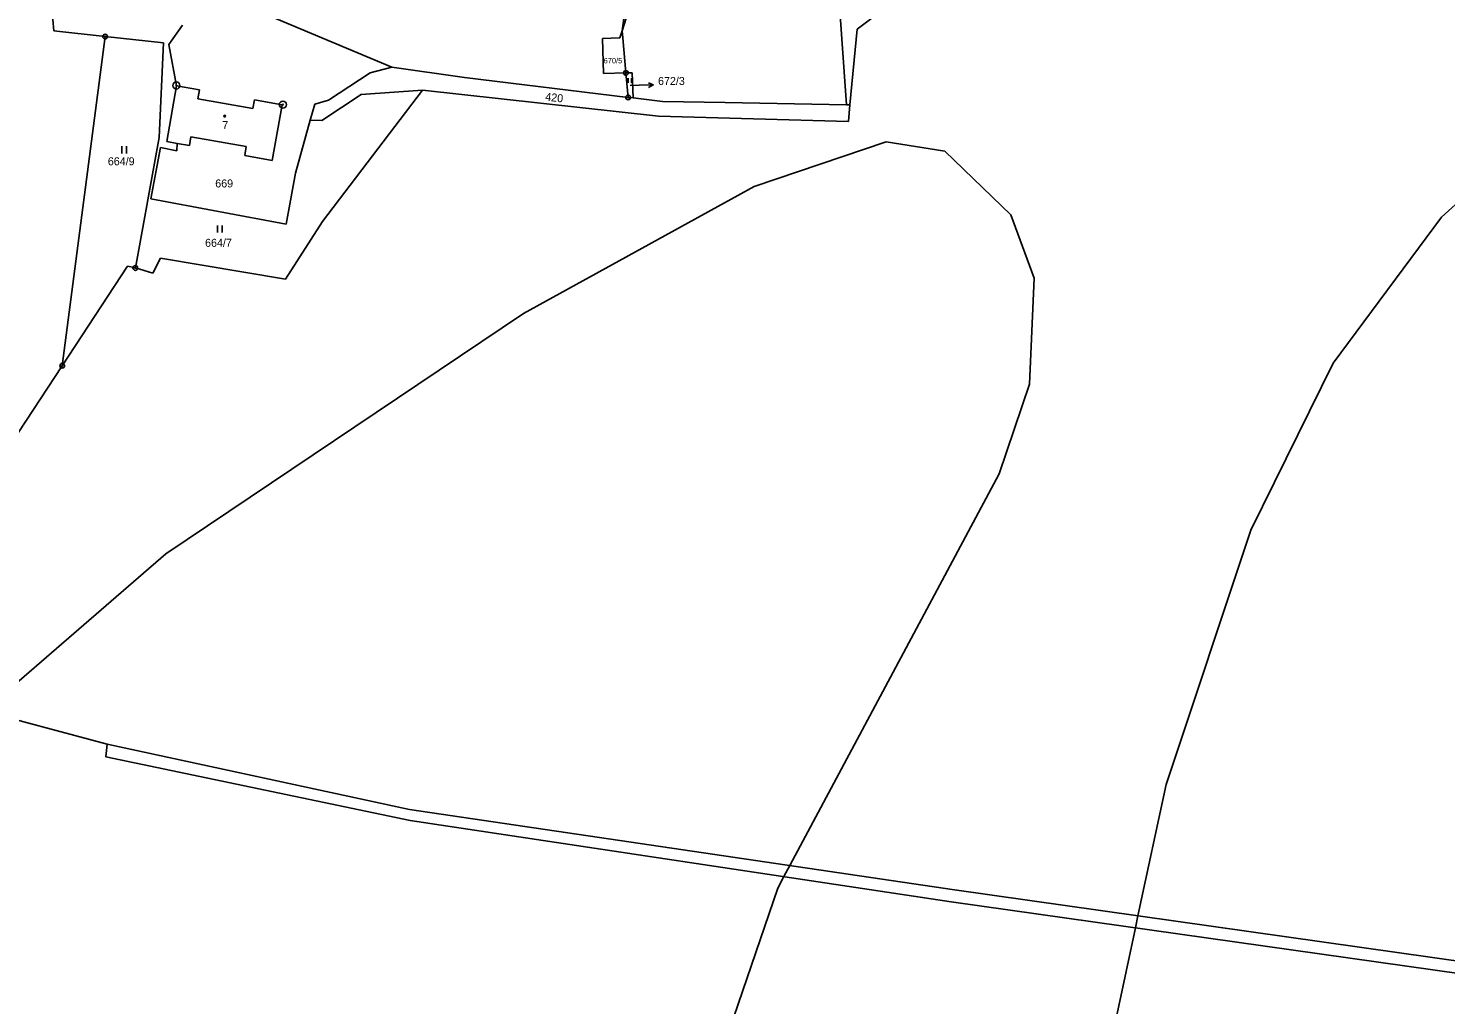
# Model space of a CAD drawing. Extents: x -547623 to -538651, y -1096714 to -1086522.
# Drawn here: x -542070.7 to -541769.6, y -1092948.3 to -1092740.9 of the extents above; entities that cross this region are included whole.
import ezdxf

# ---------------------------------------------------------------- set-up
doc = ezdxf.new("R2010")
doc.units = 0
for name, color, linetype in [('podzemní_provozovana', 7, 'Continuous'), ('Vrstva 1', 7, 'Continuous'), ('Vrstva 25', 7, 'Continuous'), ('Vrstva 52', 7, 'Continuous'), ('Vrstva 83', 7, 'Continuous'), ('Vrstva 86', 7, 'Continuous'), ('Vrstva 90', 7, 'Continuous'), ('Vrstva 92', 7, 'Continuous')]:
    doc.layers.add(name, color=color, linetype=linetype)

msp = doc.modelspace()

# ---------------------------------------------------------------- linework, layer by layer
at = {"layer": 'podzemní_provozovana'}
msp.add_line((-541940.93, -1092753), (-541937.93, -1092752.94), dxfattribs=at)
for points in [[(-541942.86, -1092753.04), (-541940.93, -1092753)], [(-541938.94, -1092752.46), (-541937.93, -1092752.94), (-541938.92, -1092753.46)]]:
    msp.add_lwpolyline(points, dxfattribs=at)
at = {"layer": 'Vrstva 1'}
for points in [[(-541854.05, -1092710.48), (-541894.65, -1092741.06)], [(-541899.99, -1092713.03), (-541896.86, -1092757.13)], [(-541940.61, -1092728.85), (-541944.56, -1092741.43)], [(-542065.87, -1092734.14), (-542065.27, -1092741.47)], [(-541993.48, -1092749.19), (-542027.57, -1092734.81)], [(-541944.56, -1092741.43), (-541943.46, -1092733.53)], [(-542065.27, -1092741.47), (-542054.37, -1092742.65)], [(-542040.84, -1092744.36), (-542037.93, -1092740.23)], [(-541944.56, -1092741.43), (-541945.03, -1092742.92)], [(-541944.43, -1092742.9), (-541944.56, -1092741.43)], [(-541896.17, -1092757.14), (-541894.65, -1092741.06)], [(-542054.37, -1092742.65), (-542063.48, -1092812.56)], [(-542054.37, -1092742.65), (-542041.94, -1092744)], [(-542041.94, -1092744), (-542042.86, -1092764.09)], [(-542039.18, -1092753.14), (-542040.84, -1092744.36)], [(-541948.72, -1092743.04), (-541945.03, -1092742.92)], [(-541948.72, -1092743.04), (-541948.48, -1092750.53)], [(-541943.74, -1092750.38), (-541944.43, -1092742.9)], [(-541998.1, -1092750.37), (-542006.89, -1092756.17)], [(-541993.48, -1092749.19), (-541998.1, -1092750.37)], [(-541993.48, -1092749.19), (-541978.01, -1092751.34)], [(-541948.48, -1092750.53), (-541943.74, -1092750.38)], [(-541943.74, -1092750.38), (-541942.39, -1092750.34)], [(-541943.28, -1092755.57), (-541943.74, -1092750.38)], [(-541942.39, -1092750.34), (-541942.22, -1092755.7)], [(-542041.28, -1092764.95), (-542039.18, -1092753.14)], [(-542039.18, -1092753.14), (-542034.35, -1092754)], [(-542034.35, -1092754), (-542034.66, -1092755.87)], [(-541943.28, -1092755.57), (-541978.01, -1092751.34)], [(-542034.66, -1092755.87), (-542022.97, -1092757.97)], [(-542022.97, -1092757.97), (-542022.63, -1092756.09)], [(-542022.63, -1092756.09), (-542016.78, -1092757.15)], [(-542006.89, -1092756.17), (-542009.85, -1092757.03)], [(-542000, -1092754.95), (-542008.37, -1092760.5)], [(-541986.96, -1092754.01), (-542008.2, -1092781.97)], [(-542000, -1092754.95), (-541986.96, -1092754.01)], [(-541986.96, -1092754.01), (-541936.84, -1092759.58)], [(-541942.22, -1092755.7), (-541943.28, -1092755.57)], [(-541935.97, -1092756.46), (-541942.22, -1092755.7)], [(-541935.97, -1092756.46), (-541922.68, -1092756.65)], [(-541922.68, -1092756.65), (-541896.86, -1092757.13)], [(-542016.78, -1092757.15), (-542018.88, -1092768.99)], [(-542010.79, -1092760.41), (-542009.85, -1092757.03)], [(-541936.84, -1092759.58), (-541896.5, -1092760.68)], [(-541896.86, -1092757.13), (-541896.17, -1092757.14)], [(-541896.5, -1092760.68), (-541896.17, -1092757.14)], [(-542013.92, -1092771.69), (-542010.79, -1092760.41)], [(-542008.37, -1092760.5), (-542010.79, -1092760.41)], [(-542042.86, -1092764.09), (-542047.95, -1092791.81)], [(-542039.09, -1092765.34), (-542041.28, -1092764.95)], [(-542039.09, -1092765.34), (-542039.15, -1092766.9)], [(-542036.48, -1092765.81), (-542039.09, -1092765.34)], [(-542036.18, -1092763.95), (-542036.48, -1092765.81)], [(-542024.43, -1092766.04), (-542036.18, -1092763.95)], [(-542024.72, -1092767.91), (-542024.43, -1092766.04)], [(-542044.64, -1092777.15), (-542042.61, -1092766.24)], [(-542042.61, -1092766.24), (-542039.15, -1092766.9)], [(-542018.88, -1092768.99), (-542024.72, -1092767.91)], [(-542013.92, -1092771.69), (-542015.93, -1092782.5)], [(-542015.93, -1092782.5), (-542044.64, -1092777.15)], [(-542016.08, -1092794.18), (-542008.2, -1092781.97)], [(-542042.6, -1092789.7), (-542044.22, -1092792.91)], [(-542016.08, -1092794.18), (-542042.6, -1092789.7)], [(-542049.6, -1092791.4), (-542063.48, -1092812.56)], [(-542047.95, -1092791.81), (-542049.6, -1092791.4)], [(-542047.95, -1092791.81), (-542044.22, -1092792.91)], [(-542086.71, -1092847.83), (-542063.48, -1092812.56)], [(-542082.51, -1092885.3), (-542053.94, -1092892.92)], [(-542053.94, -1092892.92), (-542054.19, -1092895.66)], [(-542053.94, -1092892.92), (-541989.71, -1092906.84)], [(-542054.19, -1092895.66), (-541989.59, -1092909.19)], [(-541989.71, -1092906.84), (-541873.93, -1092923.87)], [(-541989.59, -1092909.19), (-541874.66, -1092926.42)], [(-541873.93, -1092923.87), (-541756.43, -1092940.52)], [(-541874.66, -1092926.42), (-541759.8, -1092942.62)]]:
    msp.add_lwpolyline(points, dxfattribs=at)
at = {"layer": 'Vrstva 25'}
for p, q in [((-541943.27, -1092752.5), (-541943.27, -1092751.5)), ((-541942.59, -1092752.5), (-541942.59, -1092751.5)), ((-542050.8, -1092767.47), (-542050.8, -1092765.97)), ((-542049.8, -1092767.47), (-542049.8, -1092765.97)), ((-542030.5, -1092784.27), (-542030.5, -1092782.77)), ((-542029.5, -1092784.27), (-542029.5, -1092782.77))]:
    msp.add_line(p, q, dxfattribs=at)
msp.add_circle((-542028.99, -1092759.55), 0.175, dxfattribs=at)
at = {"layer": 'Vrstva 52'}
for points in [[(-541749.09, -1093162.01), (-541782, -1093167), (-541808, -1093159.5), (-541820.14, -1093146.52), (-541822.5, -1093144), (-541837, -1093117), (-541841.09, -1093095.7), (-541846.5, -1093067.5), (-541848.5, -1093022.5), (-541845.69, -1093000), (-541839.5, -1092950.5), (-541835.52, -1092931.94), (-541834.98, -1092929.39), (-541829, -1092901.5), (-541811, -1092847.5), (-541793.5, -1092812), (-541770.5, -1092781), (-541739.5, -1092753)], [(-542152, -1092973.5), (-542129.5, -1092938), (-542079.92, -1092885.99), (-542078.5, -1092884.5), (-542041.5, -1092852.5), (-541965.5, -1092801.5), (-541916.5, -1092774.5), (-541888.5, -1092765), (-541876, -1092767), (-541862, -1092780.5), (-541857, -1092794), (-541858, -1092816.5), (-541864.5, -1092835.5), (-541908.95, -1092918.72), (-541910.21, -1092921.09), (-541911.5, -1092923.5), (-541933, -1092986.5)]]:
    msp.add_lwpolyline(points, dxfattribs=at)
at = {"layer": 'Vrstva 83'}
for centre, radius in [((-542054.37, -1092742.65), 0.5), ((-542054.37, -1092742.65), 0.1), ((-541943.74, -1092750.38), 0.5), ((-541943.74, -1092750.38), 0.1), ((-542039.23, -1092753.05), 0.75), ((-542039.23, -1092753.05), 0.1), ((-542016.61, -1092757.11), 0.75), ((-542016.61, -1092757.11), 0.1), ((-541943.28, -1092755.57), 0.5), ((-541943.28, -1092755.57), 0.1), ((-542047.95, -1092791.81), 0.5), ((-542047.95, -1092791.81), 0.1), ((-542063.48, -1092812.56), 0.5), ((-542063.48, -1092812.56), 0.1)]:
    msp.add_circle(centre, radius, dxfattribs=at)
at = {"layer": 'Vrstva 90'}
for points in [[(-542041.28, -1092764.95), (-542039.18, -1092753.14)], [(-542039.18, -1092753.14), (-542034.35, -1092754)], [(-542034.35, -1092754), (-542034.66, -1092755.87)], [(-542034.66, -1092755.87), (-542022.97, -1092757.97)], [(-542022.97, -1092757.97), (-542022.63, -1092756.09)], [(-542022.63, -1092756.09), (-542016.78, -1092757.15)], [(-542016.78, -1092757.15), (-542018.88, -1092768.99)], [(-542039.09, -1092765.34), (-542041.28, -1092764.95)], [(-542036.48, -1092765.81), (-542039.09, -1092765.34)], [(-542036.18, -1092763.95), (-542036.48, -1092765.81)], [(-542024.43, -1092766.04), (-542036.18, -1092763.95)], [(-542024.72, -1092767.91), (-542024.43, -1092766.04)], [(-542018.88, -1092768.99), (-542024.72, -1092767.91)]]:
    msp.add_lwpolyline(points, dxfattribs=at)

# ---------------------------------------------------------------- texts
at = {"layer": 'podzemní_provozovana'}
msp.add_text('672/3', height=1.7, dxfattribs=at).set_placement((-541936.93, -1092752.94))
at = {"layer": 'Vrstva 86'}
for s, height, p in [('670/5', 1.14, (-541948.47, -1092748.34)), ('672/3', 0.1, (-541943.05, -1092753.04)), ('664/9', 1.7, (-542053.79, -1092770)), ('669', 1.7, (-542030.98, -1092774.7)), ('664/7', 1.7, (-542033.14, -1092787.31))]:
    msp.add_text(s, height=height, dxfattribs=at).set_placement(p)
msp.add_text('420', height=1.7, rotation=353.3278, dxfattribs=at).set_placement((-541960.95, -1092756.23))
at = {"layer": 'Vrstva 92'}
msp.add_text('7', height=1.7, dxfattribs=at).set_placement((-542029.49, -1092762.32))

doc.saveas('drawing.dxf')
